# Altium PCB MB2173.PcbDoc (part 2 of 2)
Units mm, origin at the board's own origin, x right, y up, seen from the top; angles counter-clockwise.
Board outline 55.25 x 31 mm, 2 copper layers (Top Layer, Bottom Layer), stack 0.603 mm thick; 45 components, 48 nets, 188 pads, 868 vias.
Unrouted connection lines stored in the file: 99.
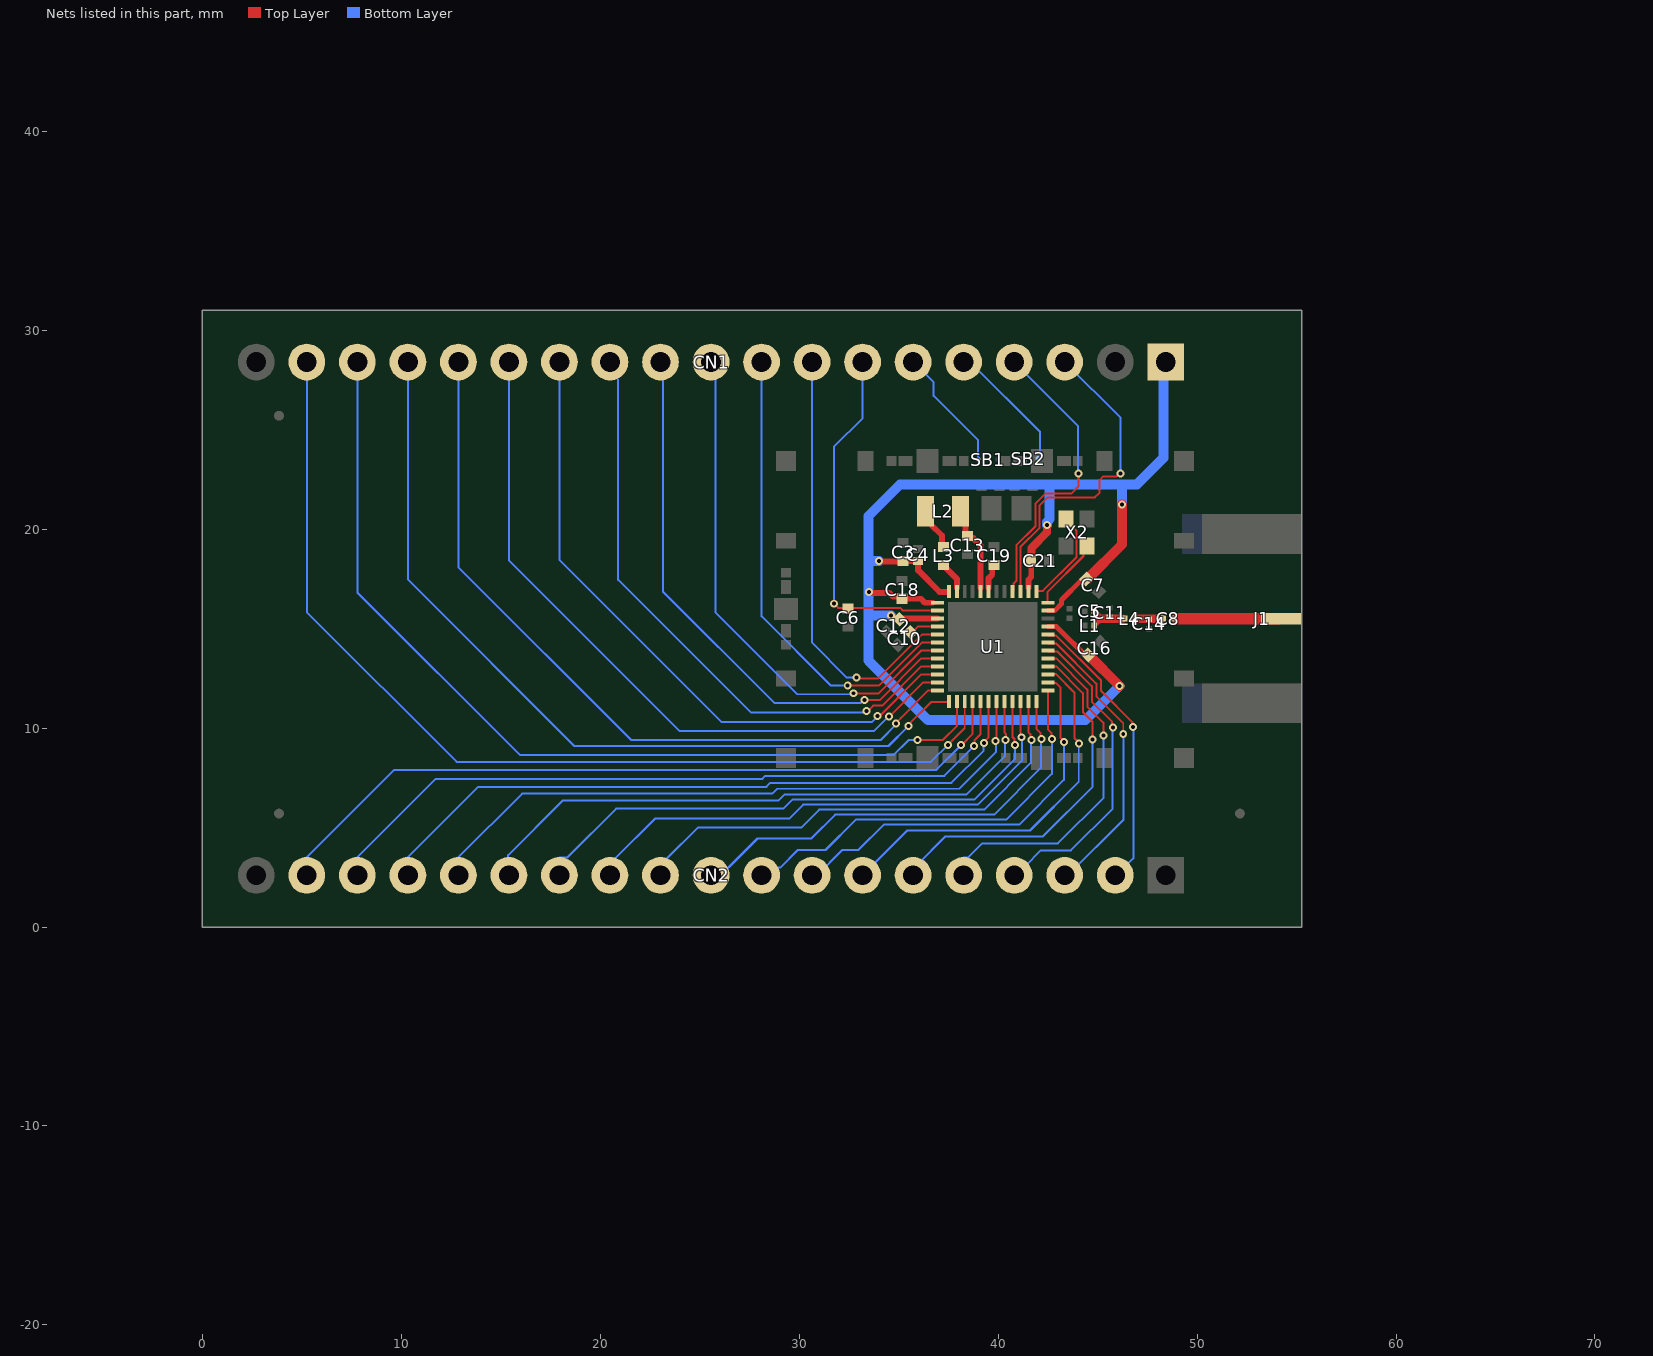
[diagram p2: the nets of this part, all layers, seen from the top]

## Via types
v1: diameter 0.4, hole 0.2, Top Layer to Bottom Layer, tented both sides, 868 vias

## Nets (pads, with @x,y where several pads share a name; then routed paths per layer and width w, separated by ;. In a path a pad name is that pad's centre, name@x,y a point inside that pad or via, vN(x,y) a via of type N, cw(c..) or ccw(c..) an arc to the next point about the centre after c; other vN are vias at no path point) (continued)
NetC5_2: C5.2 C11.2 L1.2 L4.1 | length 2.1
  Top Layer w0.28: C5.2@44.825,15.873 45.187,15.511 ; L1.2@44.826,15.149 45.187,15.51
  Top Layer w0.43: 45.187,15.5 45.597,15.5 L4.1@46.245,15.5
NetC8_1: C8.1 C14.2 L4.2 | length 1.3
  Top Layer w0.43: L4.2@46.945,15.5 47.571,15.5 C8.1@48.195,15.5
NetC8_2: C8.2 J1.1 | length 5.1
  Top Layer w0.58: 49,15.5 J1.1@54.076,15.5
NetC10_1: C10.1 U1.40 | length 1.4
  Top Layer w0.1: C10.1@35.635,14.768 35.967,15.1 U1.40@36.945,15.1
NetC13_2: C13.2 L2.1 U1.32 | length 4.4
  Top Layer w0.3: L2.1@38.292,20.9 38.292,20.283 38.35,20.225 38.35,19.7 C13.2@38.45,19.6 ; C13.2@38.45,19.65 38.555,19.545 38.755,19.545 39.1,19.2 U1.32@39.1,17.05
NetC19_2: C19.2 U1.31 | length 1.3
  Top Layer w0.3: U1.31@39.52,17.05 39.52,17.532 39.701,17.714 39.701,18.114 C19.2@39.787,18.2
NetL2_2: L2.2 L3.1 | length 2.2
  Top Layer w0.3: L2.2@36.275,20.9 36.275,20.55 36.55,20.275 36.575,20.275 37.173,19.677 37.173,19.194 L3.1@37.217,19.15
NetL3_2: L3.2 U1.35 | length 1.4
  Top Layer w0.3: L3.2@37.221,18.202 37.92,17.504 U1.35@37.92,17.05
NetU1_24: U1.24 X2.1 | length 3.5
  Top Layer w0.105: U1.24@42.495,16.3 42.487,16.307 42.487,16.85 44.287,18.65 X2.1@44.287,19.05
NetU1_25: U1.25 X2.3 | length 4.8
  Top Layer w0.1: U1.25@41.978,16.9 42.251,16.9 43.937,18.586 43.937,19.911 43.748,20.1 43.737,20.1 43.412,20.425 X2.3@43.412,20.475
PA0: CN2.9 U1.13 | length 21
  Top Layer w0.1: U1.13@42.495,11.9 42.495,9.942 42.687,9.75 42.687,9.463 v1(42.7,9.45)
  Bottom Layer w0.1: CN2.9@28.105,2.6 28.579,2.6 28.966,2.988 29.038,2.988 29.92,3.87 31.32,3.87 32.85,5.4 40.4,5.4 42.7,7.7 v1(42.7,9.45)
PA1: CN2.8 U1.14 | length 19.9
  Top Layer w0.1: U1.14@42.495,12.3 42.527,12.268 42.899,12.268 43.137,12.03 43.137,9.509 43.317,9.329 v1(43.317,9.3)
  Bottom Layer w0.1: CN2.8@30.645,2.6 30.9,2.6 32.17,3.87 32.97,3.87 34.25,5.15 41.05,5.15 43.3,7.4 v1@43.3,9.148
PA2: CN2.7 U1.15 | length 19
  Top Layer w0.1: U1.15@42.495,12.7 42.501,12.706 42.911,12.706 43.837,11.78 43.837,9.484 44.058,9.262 v1(44.058,9.225)
  Bottom Layer w0.1: CN2.7@33.262,2.689 35.424,4.85 41.6,4.85 44.05,7.3 44.05,9.217 v1(44.058,9.225)
PA3: CN2.6 U1.16 | length 17.5
  Top Layer w0.1: U1.16@42.645,13.1 42.917,13.1 44.258,11.759 44.258,10.809 44.737,10.33 v1(44.737,9.422)
  Bottom Layer w0.1: CN2.6@35.908,3.107 37.35,4.55 42.25,4.55 44.75,7.05 v1@44.75,9.359
PA4: CN2.5 U1.17 | length 16.6
  Top Layer w0.1: U1.17@42.495,13.5 42.922,13.5 44.487,11.935 44.487,11.08 45.289,10.278 v1(45.289,9.617)
  Bottom Layer w0.1: CN2.5@38.265,3.5 38.5,3.5 39.2,4.2 43,4.2 45.3,6.5 v1@45.3,9.492
PA5: CN2.4 U1.18 | length 15
  Top Layer w0.1: U1.18@42.495,13.9 42.545,13.85 42.967,13.85 44.712,12.105 44.712,11.325 45.723,10.314 45.723,10.083 v1(45.781,10.026)
  Bottom Layer w0.1: CN2.4@41.356,3.056 42.15,3.85 43.65,3.85 45.75,5.95 v1@45.75,9.847
PA6: CN2.3 U1.19 | length 14.8
  Top Layer w0.1: U1.19@42.495,14.3 42.545,14.25 42.917,14.25 44.937,12.23 44.937,11.6 46.287,10.25 v1(46.287,9.7)
  Bottom Layer w0.1: CN2.3@43.345,2.6 43.504,2.6 46.3,5.396 v1@46.3,9.694
PA7: CN2.2 U1.20 | length 14.5
  Top Layer w0.1: U1.20@42.495,14.7 42.545,14.65 42.917,14.65 45.167,12.4 45.167,11.87 46.74,10.297 46.74,10.098 v1(46.787,10.05)
  Bottom Layer w0.1: CN2.2@45.885,2.6 45.95,2.6 46.8,3.45 v1@46.8,10.022
PA8: CN2.10 U1.12 | length 22.2
  Top Layer w0.1: U1.12@41.92,11.325 41.92,9.967 42.137,9.75 42.137,9.48 v1(42.167,9.45)
  Bottom Layer w0.1: CN2.10@25.565,2.6 26.039,2.6 26.456,3.018 26.468,3.018 27.9,4.45 30.6,4.45 31.8,5.65 39.8,5.65 42.15,8 v1@42.15,9.372
PA9: CN2.11 U1.11 | length 23.2
  Top Layer w0.1: U1.11@41.52,11.175 41.52,9.8 41.62,9.7 41.62,9.45 v1(41.67,9.4)
  Bottom Layer w0.1: CN2.11@23.328,3.428 24.9,5 30.1,5 31,5.9 39.3,5.9 41.648,8.248 v1@41.648,9.278
PA10: CN2.12 U1.10 | length 25.4
  Top Layer w0.1: U1.10@41.12,11.325 41.12,9.587 v1(41.168,9.539)
  Bottom Layer w0.1: CN2.12@20.774,3.474 22.75,5.45 29.5,5.45 30.2,6.15 38.981,6.15 41.17,8.339 ; v1(41.168,9.539) 41.187,9.52 41.187,8.38
PA11: CN2.13 U1.9 | length 27.7
  Top Layer w0.1: U1.9@40.72,11.175 40.72,9.55 40.82,9.45 40.82,9.167 v1(40.837,9.15)
  Bottom Layer w0.1: CN2.13@17.945,3.5 18.35,3.5 20.8,5.95 29.2,5.95 29.65,6.4 38.8,6.4 40.837,8.437 v1(40.837,9.15)
PA12: CN2.14 U1.8 | length 30.4
  Top Layer w0.1: U1.8@40.32,11.325 40.32,9.768 40.391,9.696 40.391,9.426 v1(40.37,9.404)
  Bottom Layer w0.1: CN2.14@15.015,3.265 15.223,3.265 15.366,3.408 15.366,3.616 18.1,6.35 28.95,6.35 29.25,6.65 38.4,6.65 40.337,8.587 40.337,9.372 v1(40.37,9.404)
PA13: CN2.15 U1.7 | length 31.8
  Top Layer w0.1: v1(39.873,9.348) 39.92,9.395 U1.7@39.92,11.325
  Bottom Layer w0.1: CN2.15@12.865,3.5 16.065,6.7 28.65,6.7 28.9,6.95 38.05,6.95 39.887,8.787 39.887,9.334 v1(39.873,9.348)
PA14: CN2.16 U1.6 | length 33.7
  Top Layer w0.1: v1(39.287,9.25) 39.287,9.309 39.52,9.542 U1.6@39.52,11.325
  Bottom Layer w0.1: CN2.16@10.325,3.5 13.875,7.05 28.35,7.05 28.55,7.25 37.65,7.25 39.265,8.865 39.265,9.228 v1(39.287,9.25)
PA15: CN2.17 U1.5 | length 35.5
  Top Layer w0.1: v1(38.787,9.1) 38.817,9.13 38.817,9.4 39.12,9.702 U1.5@39.12,11.175
  Bottom Layer w0.1: CN2.17@7.785,3.5 11.735,7.45 28.15,7.45 28.3,7.6 37.3,7.6 v1@38.802,9.102
PB0: CN2.18 U1.4 | length 37.6
  Top Layer w0.1: v1(38.137,9.15) 38.162,9.15 38.72,9.707 U1.4@38.72,11.325
  Bottom Layer w0.1: CN2.18@5.245,3.5 9.645,7.9 36.887,7.9 v1@38.087,9.1
PB1: CN1.18 U1.3 | length 49.8
  Top Layer w0.1: v1(37.467,9.15) 38.32,10.002 U1.3@38.32,11.175
  Bottom Layer w0.1: CN1.18@5.245,27.5 5.245,15.833 12.778,8.3 36.617,8.3 v1@37.53,9.213
PB2: CN1.17 U1.2 | length 46
  Top Layer w0.1: v1(35.937,9.4) 37.217,9.4 37.92,10.102 U1.2@37.92,11.325
  Bottom Layer w0.1: CN1.17@7.785,27.5 7.785,16.815 15.95,8.65 34.761,8.65 35.511,9.4 v1(35.937,9.4)
PB3: CN1.16 U1.1 | length 41.7
  Top Layer w0.1: v1(35.487,10.1) 35.487,10.17 36.624,11.307 37.501,11.307 U1.1@37.52,11.325
  Bottom Layer w0.1: CN1.16@10.325,27.5 10.325,17.475 18.7,9.1 34.487,9.1 v1(35.487,10.1)
PB4: CN1.15 U1.48 | length 38.2
  Top Layer w0.1: v1(34.868,10.219) 34.868,10.274 35.124,10.529 36.495,11.9 U1.48@36.945,11.9
  Bottom Layer w0.1: CN1.15@12.865,27.5 12.865,18.085 21.55,9.4 34.087,9.4 34.868,10.181 v1(34.868,10.219)
PB5: CN1.14 U1.47 | length 35
  Top Layer w0.1: v1(34.515,10.573) 36.242,12.3 U1.47@36.794,12.3
  Bottom Layer w0.1: CN1.14@15.405,27.5 15.405,18.445 24,9.85 33.756,9.85 34.479,10.573 v1(34.515,10.573)
PB6: CN1.13 U1.46 | length 32.3
  Top Layer w0.1: v1(33.937,10.6) 34.018,10.6 34.116,10.697 34.134,10.697 36.137,12.7 U1.46@36.794,12.7
  Bottom Layer w0.1: CN1.13@17.945,27.5 17.945,18.455 26.1,10.3 33.637,10.3 v1(33.937,10.6)
PB7: CN1.12 U1.45 | length 30.6
  Top Layer w0.1: v1(33.387,10.85) 33.437,10.85 33.718,11.131 34.168,11.131 36.137,13.1 U1.45@36.794,13.1
  Bottom Layer w0.1: CN1.12@20.55,28.25 20.55,27.862 20.9,27.512 20.9,17.45 27.565,10.785 33.178,10.785 33.186,10.793 33.33,10.793 v1(33.387,10.85)
PB8: CN1.11 U1.44 | length 28.5
  Top Layer w0.1: v1(33.287,11.4) 34.037,11.4 36.137,13.5 U1.44@36.794,13.5
  Bottom Layer w0.1: CN1.11@23.025,28.4 23.15,28.275 23.15,16.862 28.762,11.25 33.078,11.25 33.228,11.4 v1(33.287,11.4)
PB9: CN1.10 U1.43 | length 26.3
  Top Layer w0.1: v1(32.737,11.75) 33.987,11.75 36.137,13.9 U1.43@36.794,13.9
  Bottom Layer w0.1: CN1.10@25.565,28.4 25.8,28.165 25.8,15.8 29.9,11.7 32.687,11.7 v1(32.737,11.75)
PB10: CN1.9 U1.42 | length 23.8
  Top Layer w0.1: v1(32.437,12.15) 34.017,12.15 36.167,14.3 U1.42@36.794,14.3
  Bottom Layer w0.1: CN1.9@28.105,28.4 28.105,15.615 31.571,12.15 v1(32.437,12.15)
PB11: CN1.8 U1.41 | length 21.9
  Top Layer w0.1: v1(32.887,12.55) 32.937,12.5 33.967,12.5 36.167,14.7 U1.41@36.794,14.7
  Bottom Layer w0.1: CN1.8@30.645,28.4 30.645,14.292 32.397,12.54 32.877,12.54 v1(32.887,12.55)
PB12: CN1.6 SB1.1 | length 6.4
  Bottom Layer w0.1: CN1.6@35.725,28.4 36.75,27.375 36.75,26.7 38.987,24.463 38.987,23.7 SB1.1@38.987,23.4
PB13: CN1.5 SB2.1 | length 6.8
  Bottom Layer w0.1: CN1.5@38.265,28.4 38.6,28.4 42.102,24.898 42.102,23.396
PB14: CN1.4 U1.28 | length 14.9
  Top Layer w0.1: U1.28@40.72,16.875 40.77,16.925 40.77,17.252 40.917,17.4 40.917,19.183 41.867,20.133 41.867,21.28 42.387,21.8 43.687,21.8 44.037,22.15 v1(44.037,22.8)
  Bottom Layer w0.1: CN1.4@40.805,28.4 44.008,25.197 v1@44.008,22.902
PB15: CN1.3 U1.27 | length 16.5
  Top Layer w0.1: U1.27@41.12,17.025 41.12,19.102 42.067,20.05 42.067,21.18 42.487,21.6 44.859,21.6 45.098,21.839 45.098,22.461 45.287,22.65 45.94,22.65 46.09,22.8 v1(46.148,22.8)
  Bottom Layer w0.1: CN1.3@43.345,28.4 46.15,25.595 v1@46.15,22.758
RSTN: C6.1 CN1.7 U1.38 | length 18.2
  Top Layer w0.1: v1(31.737,16.25) 31.751,16.25 31.956,16.045 35.069,16.045 35.214,15.9 U1.38@36.945,15.9
  Bottom Layer w0.1: v1(31.737,16.25) 31.737,23.15 ; 31.737,23.044 31.737,24.137 33.185,25.585 33.185,26.55 CN1.7@33.185,28.4
VDD: C3.2 C4.2 C7.2 C12.2 C16.2 C18.2 C21.2 CN1.1 U1.21 U1.23 U1.26 U1.36 U1.37 U1.39 | length 80.5
  Top Layer w0.2: U1.37@36.72,16.3 U1.37@36.945,16.3
  Top Layer w0.25: U1.23@42.495,15.9 42.838,15.9 43.183,16.245 43.183,16.439 44.194,17.451 44.414,17.451 C7.2@44.432,17.468 ; U1.21@42.497,15.1 42.936,15.1 C16.2@44.513,13.523
  Top Layer w0.29: U1.26@41.52,17.055 41.52,17.459 41.667,17.606 C21.2@41.667,18.4
  Top Layer w0.3: v1@33.563,16.831 33.594,16.8 34.519,16.8 34.714,16.605 35.062,16.605 C18.2@35.167,16.5 ; v1(34.017,18.4) 34.036,18.381 34.454,18.381 C3.2@35.011,18.38 ; v1@34.646,15.686 34.646,15.648 34.663,15.631 34.724,15.631 34.887,15.468 C12.2@35.035,15.468 ; C12.2@35.152,15.5 U1.39@36.945,15.5 ; C18.2@35.197,16.5 36.117,16.5 36.317,16.3 U1.37@36.72,16.3 ; C3.2@35.217,18.5 35.317,18.4 C4.2@35.967,18.4 ; C4.2@35.959,18.4 35.974,18.385 35.974,17.926 37.05,16.85 U1.36@37.47,16.85
  Top Layer w0.4: C21.2@41.673,18.423 41.673,19.057 42.447,19.831 v1(42.447,20.2)
  Top Layer w0.5: C7.2@44.5,17.504 46.217,19.221 v1(46.217,21.25) ; C16.2@44.519,13.682 44.526,13.682 v1(46.1,12.109)
  Bottom Layer w0.5: 33.517,18.4 v1(34.017,18.4) ; v1(34.617,15.65) 33.475,15.65 ; v1(42.447,20.2) 42.447,20.36 42.587,20.5 42.587,22.2 ; v1(46.1,12.109) 44.391,10.4 36.461,10.4 33.475,13.386 33.475,15.65 ; v1(46.217,21.25) 46.217,22.1 ; CN1.1@48.425,28.4 48.3,28.275 48.3,23.581 46.969,22.25 46.217,22.25 42.587,22.25 ; 33.475,15.65 33.475,20.658 35.067,22.25 ; 35.067,22.25 42.587,22.25 ; 35.067,22.25 42.587,22.25
  other v1: 33.517,16.85
pads on no net: U1.33

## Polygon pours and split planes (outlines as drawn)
GND on Bottom Layer "NONET_L-01_P-001" (solid, remove dead copper, pour order 0): 0,31 0,0 55.25,0 55.25,31
GND on Top Layer "NONET_L-01_P-001" (solid, remove dead copper, pour order 1): 0,31 0,0 55.25,0 55.25,31

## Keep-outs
Keep-Out Layer:
  lines w0.1: -0.05,0 ccw(c0,0) 0,-0.05 ; -0.05,0 ccw(c0,0) 0,-0.05 ; -0.05,0 -0.05,31 ; -0.05,31 cw(c0,31) 0,31.05 ; -0.05,31 cw(c0,31) 0,31.05 ; 0,-0.05 55.25,-0.05 ; 0,31.05 55.25,31.05 ; 55.25,-0.05 ccw(c55.25,0) 55.3,0 ; 55.25,-0.05 ccw(c55.25,0) 55.3,0 ; 55.25,31.05 cw(c55.25,31) 55.3,31 ; 55.25,31.05 cw(c55.25,31) 55.3,31 ; 55.3,0 55.3,31

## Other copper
Top Layer:
  pour cut-out: 44.794,15.149 48.835,15.149 48.835,15.851 44.795,15.851
  pour cut-out: 44.587,15.775 41.97,15.775 41.97,15.225 44.587,15.225
  region net GND: 43.9,15.775 43.975,15.85 43.975,16.462 43.749,16.688 43.408,16.346 43.408,15.775
  region net GND: 43.9,16.202 43.486,16.202 43.059,15.775 43.9,15.775
  pour cut-out: 48.835,15.99 48.63,15.785 48.63,15.215 48.835,15.01 55.461,15.01 55.461,15.99
  pour cut-out: 36.775,20.025 36.775,21.775 40.65,21.775 40.65,20.025
  pour cut-out: 38.22,17.1 38.42,17.1 38.42,16.55 38.22,16.55
  pour cut-out: 34.217,18.394 34.217,20.1 34.441,20.1 34.441,18.394
  region net GND: 43.939,14.773 43.586,14.773 43.135,15.225 43.939,15.225
  pour cut-out: 42.996,15.736 43.246,15.986 43.175,16.057 42.925,15.807
  pour cut-out: 43.255,16.193 43.902,16.841 43.832,16.911 43.184,16.264
  pour cut-out: 43.736,16.701 44.001,16.436 44.171,16.606 43.907,16.872
  pour cut-out: 43.976,16.606 43.974,15.35 44.169,15.35 44.171,16.606
  pour cut-out: 34.292,20.1 36.842,20.1 36.842,19.95 34.292,19.95
  pour cut-out: 37.275,16.625 42.241,16.625 42.241,11.554 37.275,11.554
  region net GND: 54.752,14.913 55.138,14.913 55.138,15.002 54.752,15.002
  text ".Layer_Name" at 9.099,-12.163 h3
  text ".GTL" at 50.793,-12.163 h3
Bottom Layer:
  pour cut-out: 45.824,9.325 45.348,9.325 45.347,4.85 45.824,4.85
  pour cut-out: 30.5,4.473 30.5,4.95 27.931,4.95 27.931,4.474
  pour cut-out: 30.75,3.924 30.75,4.4 29.881,4.4 29.881,3.924
  pour cut-out: 31.076,3.976 32.025,4.925 30.938,6.012 29.989,5.064
  text ".GBL" at 39.59,-12.195 h3
  text ".Layer_Name" at 80.904,-12.195 h3

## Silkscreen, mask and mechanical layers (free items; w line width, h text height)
Top Overlay:
  lines w0.1: 43.037,17.221 43.037,16.127 43.153,16.012
  lines w0.2: 37.04,17.75 37.488,17.75
  text "MB2173" at 11.819,20.569 h3 r270
  text ".Layer_Name" at 9.099,-12.163 h3
  text ".GTO" at 50.793,-12.163 h3
Bottom Overlay:
  text "RSTN" at 33.312,24.135 h0.64 r270
  text "GND" at 46.012,24.135 h0.64 r270
  text "VDD" at 48.552,24.135 h0.64 r270
  text "PA10" at 20.612,5.151 h0.64 r270
  text "TX" at 23.152,5.151 h0.64 r270
  text "RX" at 25.692,5.151 h0.64 r270
  text "SWCLK" at 35.852,5.151 h0.64 r270
  text "GND" at 48.552,5.151 h0.64 r270
  text "SWDIO" at 33.185,5.024 h0.64 r270
  text ".GBO" at 39.59,-12.195 h3
  text ".Layer_Name" at 80.904,-12.195 h3
Top Paste:
  text ".Layer_Name" at 9.099,-12.163 h3
  text ".GTP" at 50.793,-12.163 h3
Bottom Paste:
  text ".GBP" at 39.59,-12.195 h3
  text ".Layer_Name" at 80.904,-12.195 h3
Top Solder:
  text ".Layer_Name" at 9.099,-12.163 h3
  text ".GTS" at 50.793,-12.163 h3
Bottom Solder:
  text ".GBS" at 39.59,-12.195 h3
  text ".Layer_Name" at 80.904,-12.195 h3
Mechanical 1:
  lines w0.1: 55.25,0 55.25,31 ; 55.25,0 55.25,0 ; 55.25,0 0,0 0,31 55.25,31 ; 55.25,31 55.25,31 ; 55.25,31 55.25,31
Bottom Assembly:
  text ".Layer_Name" at 9.099,-12.163 h3
  text ".GM2" at 50.793,-12.163 h3
Mechanical 14:
  text ".Layer_Name" at 9.099,-12.163 h3
  text ".GM14" at 50.793,-12.163 h3
Mechanical 15:
  circle w0.2: c-4.1,-10.71 r0.61
  circle w0.2: c-4.1,-10.71 r1.205
  circle w0.2: c-4.1,41.628 r0.61
  circle w0.2: c-4.1,41.628 r1.205
  circle w0.2: c68.8,15.54 r1.205
  circle w0.2: c68.8,15.54 r0.61
  lines w0.2: -6.2,-10.71 -2,-10.71 ; -6.2,41.628 -2,41.628 ; -4.1,-12.8 -4.1,-8.61 ; -4.1,39.538 -4.1,43.728 ; 66.7,15.54 70.9,15.54 ; 68.8,13.45 68.8,17.64
  text ".GM15" at 39.59,-12.195 h3
  text ".Layer_Name" at 80.904,-12.195 h3
Drill Drawing:
  drawing of 159 lines, arcs and shapes, not listed
  text "Symbol" at 2.427,89.563 h1.83
  text "Count" at 15.276,89.563 h1.83
  text "Hole Size" at 30.512,89.563 h1.83
  text "Plated" at 58.19,89.563 h1.83
  text "Hole Type" at 71.039,89.563 h1.83
  text "Drill Layer Pair" at 89.677,89.563 h1.83
  text "Via/Pad" at 127.766,89.563 h1.83
  text "Pad Shape" at 142.748,89.563 h1.83
  text "Template" at 161.691,89.563 h1.83
  text "868" at 15.276,85.753 h1.52
  text "0.200mm (7.87mil)" at 30.512,85.753 h1.52
  text "PTH" at 58.19,85.753 h1.52
  text "Round" at 71.039,85.753 h1.52
  text "Top Layer - Bottom Layer" at 89.677,85.753 h1.52
  text "Via" at 127.766,85.753 h1.52
  text "Rounded" at 142.748,85.753 h1.52
  text "v40h20m0mx0" at 161.691,85.753 h1.52
  text "38" at 15.276,81.943 h1.52
  text "1.000mm (39.37mil)" at 30.512,81.943 h1.52
  text "PTH" at 58.19,81.943 h1.52
  text "Round" at 71.039,81.943 h1.52
  text "Top Layer - Bottom Layer" at 89.677,81.943 h1.52
  text "Pad" at 127.766,81.943 h1.52
  text "Rounded" at 142.748,81.943 h1.52
  text "(Mixed)" at 161.691,81.943 h1.52
  text "906 Total" at 15.276,78.133 h1.52
  text "PCB SPECIFICATIONS :" at 1.133,70.47 h3
  text "A.   MATERIAL :" at 1.133,66.47 h3
  text "FR-4" at 39.633,66.47 h3
  text "X  TG-170" at 56.133,66.47 h3
  text "TG-150" at 74.383,66.47 h3
  text "TG-140" at 90.383,66.47 h3
  text "B.   MATERIAL FAMILY :" at 1.133,63.47 h3
  text "N/A" at 39.633,63.47 h3
  text "C.   SOLDERMASK COLOR :" at 1.133,60.47 h3
  text "X   GREEN" at 39.633,60.47 h3
  text "BLUE" at 56.133,60.47 h3
  text "RED" at 74.383,60.47 h3
  text "BLACK" at 90.383,60.47 h3
  text "D.   SILKSCREEN COLOR :" at 1.133,57.47 h3
  text "X  WHITE" at 39.633,57.47 h3
  text "YELLOW" at 56.133,57.47 h3
  text "BLACK" at 74.383,57.47 h3
  text "E.   SURFACE FINISH :" at 1.133,54.47 h3
  text "X  ENIG" at 39.633,54.47 h3
  text "IMMERSION SILVER" at 56.133,54.47 h3
  text "IMMERSION TIN" at 90.383,54.47 h3
  text "HASL" at 39.633,51.47 h3
  text "HASL (PB-FREE)" at 56.133,51.47 h3
  text "GOLDEN FINGER" at 90.383,51.47 h3
  text "F.   IMPEDANCE CONTROL :" at 1.133,48.47 h3
  text "NO" at 39.633,48.47 h3
  text "X  YES  (SEE IMPEDANCE TABLE FOR DETAIL INFORMATION)" at 56.133,48.47 h3
  text "G.   THROUGH VIA :" at 1.133,45.47 h3
  text "PLUG THE VIAS WHICH ARE COVERED WITH SOLDERMASK ONE OR TWO SIDE." at 39.633,45.47 h3
  text "PLUG MATERIAL :" at 39.633,42.47 h3
  text "X  SOLDERMASK" at 65.133,42.47 h3
  text "NON-CONDUCTIVE EPOXY." at 90.383,42.47 h3
  text "H.   STACK-UP :" at 1.133,39.47 h3
  text "SEE LAYER STACK-UP SEQUENCE FOR OVERALL THICKNESS." at 39.633,39.47 h3
  text "Layer" at 79.377,27.646 h1.52
  text "Name" at 89.788,27.646 h1.52
  text "Material" at 113.404,27.646 h1.52
  text "Thickness" at 141.59,27.646 h1.52
  text "Constant" at 158.096,27.646 h1.52
  text "Top Overlay" at 89.788,24.598 h1.52
  text "Top Solder" at 89.788,21.55 h1.52
  text "Solder Resist" at 113.404,21.55 h1.52
  text "0.020mm" at 141.59,21.55 h1.52
  text "3.5" at 158.096,21.55 h1.52
  text "1" at 79.377,18.502 h1.52
  text "Top Layer" at 89.788,18.502 h1.52
  text "0.035mm" at 141.59,18.502 h1.52
  text "Dielectric 1" at 89.788,15.454 h1.52
  text "TU-768 (3 x 7628)" at 113.404,15.454 h1.52
  text "0.533mm" at 141.59,15.454 h1.52
  text "4.6" at 158.096,15.454 h1.52
  text "2" at 79.377,12.406 h1.52
  text "Bottom Layer" at 89.788,12.406 h1.52
  text "0.035mm" at 141.59,12.406 h1.52
  text "Bottom Solder" at 89.788,9.358 h1.52
  text "Solder Resist" at 113.404,9.358 h1.52
  text "0.020mm" at 141.59,9.358 h1.52
  text "3.5" at 158.096,9.358 h1.52
  text "Bottom Overlay" at 89.788,6.31 h1.52
  text "(mm)" at 113.45,-8.484 h3
  text "(mm)" at 123.85,-8.584 h3
  text ".Layer_Name" at 9.099,-12.163 h3
  text ".DRL" at 50.793,-12.163 h3
Mechanical 20:
  circle w0.254: c87.103,-18.884 r1.3
  region: 72.625,-19.977 61.869,-19.977 62.862,-17.484 70.72,-17.484 71.169,-16.725 73.377,-19.273
  region: 86.628,-11.647 71.101,-11.647 70.407,-13.423 69.196,-14.648 67.799,-12.788 67.799,-11.137 68.942,-9.74 70.378,-9.361 86.628,-9.361
  lines w0.254: 62.862,-17.484 71.654,-17.484 68.588,-13.946 cw(c70.392,-12.002) 70.632,-9.361 87.396,-9.361 86.634,-11.647 ; 66.176,-9.114 cw(c68.602,-10.085) 68.839,-7.482 ; 66.215,-9.082 61.869,-19.977 81.191,-19.977 ccw(c81.44,-17.242) 83.989,-18.262 ; 67.955,-13.017 73.377,-19.273 ; 68.209,-13.017 73.514,-19.138 ; 68.209,-12.763 73.514,-18.884 ; 68.307,-11.647 81.3,-11.647 ; 68.336,-12.636 73.641,-18.757 ; 68.463,-12.509 73.768,-18.63 ; 68.59,-12.382 73.895,-18.503 ; 68.717,-12.255 74.022,-18.376 ; 68.772,-10.302 74.077,-16.423 ; 68.84,-7.482 88.29,-7.482 83.99,-18.26 ; 68.844,-12.128 74.094,-18.186 ; 68.844,-11.874 74.149,-17.995 ; 68.844,-11.62 74.149,-17.741 ; 68.844,-10.731 74.149,-16.852 ; 68.971,-11.493 74.276,-17.614 ; 68.971,-11.112 74.276,-17.233 ; 70.343,-17.497 ccw(c70.448,-16.962) 70.745,-16.505 ; 71.429,-11.634 ccw(c71.403,-12.201) 71.073,-12.663 73.438,-15.392 cw(c71.634,-17.336) 72.366,-19.885 ; 77.71,-19.773 80.6,-11.393 ; 77.933,-19.723 80.802,-11.402 ; 78.06,-19.723 80.929,-11.402 ; 78.314,-19.723 81.183,-11.402 ; 78.568,-19.723 81.437,-11.402 ; 78.822,-19.723 81.691,-11.402 ; 79.076,-19.723 81.945,-11.402 ; 79.33,-19.723 82.199,-11.402 ; 79.584,-19.723 82.453,-11.402 ; 79.838,-19.723 82.707,-11.402 ; 80.046,-19.773 82.936,-11.393 ; 82.936,-11.647 86.628,-11.647 ; 85.96,-11.645 86.722,-9.359 ; 86.126,-11.647 86.888,-9.361 ; 86.38,-11.647 87.142,-9.361
  lines w0.3: 0.098,-23.863 90.098,-23.863 90.098,-3.863 0.098,-3.863 ; 0.098,-18.863 60.098,-18.863 ; 0.098,-13.863 60.098,-13.863 ; 0.098,-8.863 60.098,-8.863 ; 0.099,-23.863 0.099,-3.863 ; 40.098,-23.863 40.098,-8.863 ; 60.098,-23.863 60.098,-3.863 ; 77.71,-19.773 80.046,-19.773
  text "Project: '.Board_Name'" at 1.099,-7.079 h3
  text "Layer:" at 1.099,-12.163 h3
  text "Gerber:" at 41.087,-12.163 h3
  text "Variant: '.VariantName'" at 1.099,-17.163 h3
  text "Ref: '.Board_Reference'" at 41.214,-17.163 h3
  text "R" at 86.595,-19.646 h1.52
  text "Date: '.Board_Document_Date'" at 1.099,-22.163 h3
  text "Rev: '.Board_PCB_Revision'" at 41.157,-22.163 h3
Mechanical 21:
  circle w0.254: c3.281,-18.884 r1.3
  region: 3.756,-11.647 19.283,-11.647 19.978,-13.423 21.188,-14.648 22.585,-12.788 22.585,-11.137 21.442,-9.74 20.006,-9.361 3.756,-9.361
  region: 17.759,-19.977 28.515,-19.977 27.522,-17.484 19.664,-17.484 19.216,-16.725 17.007,-19.273
  lines w0.254: 3.242,-9.361 4.004,-11.647 ; 3.496,-9.361 4.258,-11.647 ; 3.662,-9.359 4.424,-11.645 ; 3.75,-11.647 2.988,-9.361 19.752,-9.361 cw(c19.992,-12.002) 21.796,-13.946 18.73,-17.484 27.522,-17.484 ; 3.756,-11.647 7.448,-11.647 ; 6.394,-18.26 2.095,-7.482 21.544,-7.482 ; 6.395,-18.262 ccw(c8.944,-17.242) 9.193,-19.977 28.515,-19.977 24.169,-9.082 ; 7.448,-11.393 10.338,-19.773 ; 7.677,-11.402 10.546,-19.723 ; 7.931,-11.402 10.8,-19.723 ; 8.185,-11.402 11.054,-19.723 ; 8.439,-11.402 11.308,-19.723 ; 8.693,-11.402 11.562,-19.723 ; 8.947,-11.402 11.816,-19.723 ; 9.084,-11.647 22.077,-11.647 ; 9.201,-11.402 12.07,-19.723 ; 9.455,-11.402 12.324,-19.723 ; 9.582,-11.402 12.451,-19.723 ; 9.784,-11.393 12.674,-19.773 ; 16.108,-17.614 21.413,-11.493 ; 16.108,-17.233 21.413,-11.112 ; 16.235,-17.995 21.54,-11.874 ; 16.235,-17.741 21.54,-11.62 ; 16.235,-16.852 21.54,-10.731 ; 16.29,-18.186 21.54,-12.128 ; 16.308,-16.423 21.613,-10.302 ; 16.362,-18.376 21.667,-12.255 ; 16.489,-18.503 21.794,-12.382 ; 16.616,-18.63 21.921,-12.509 ; 16.743,-18.757 22.048,-12.636 ; 16.87,-19.138 22.175,-13.017 ; 16.87,-18.884 22.175,-12.763 ; 17.007,-19.273 22.429,-13.017 ; 18.018,-19.885 cw(c18.75,-17.336) 16.946,-15.392 19.311,-12.663 ccw(c18.981,-12.201) 18.955,-11.634 ; 19.639,-16.505 ccw(c19.937,-16.962) 20.042,-17.497 ; 21.546,-7.482 cw(c21.782,-10.085) 24.208,-9.114
  lines w0.3: 10.338,-19.773 12.674,-19.773 ; 30.098,-23.863 30.098,-3.863 ; 30.098,-18.863 90.098,-18.863 ; 30.098,-13.863 90.098,-13.863 ; 30.098,-8.863 90.098,-8.863 ; 50.098,-23.863 50.098,-8.863 ; 0.098,-23.863 0.098,-3.863 90.098,-3.863 90.098,-23.863 0.098,-23.863
  text "Project: '.Board_Name'" at 88.904,-7.079 h3
  text "Gerber:" at 48.916,-12.163 h3
  text "Layer:" at 88.904,-12.163 h3
  text "Ref: '.Board_Reference'" at 48.916,-17.163 h3
  text "Variant: '.VariantName'" at 88.904,-17.163 h3
  text "R" at 3.789,-19.646 h1.52
  text "Rev: '.Board_PCB_Revision'" at 48.973,-22.163 h3
  text "Date: '.Board_Document_Date'" at 88.904,-22.163 h3

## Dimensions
0,31 to 55.25,31 on Mechanical 16
0,31 to 0,0 on Mechanical 16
